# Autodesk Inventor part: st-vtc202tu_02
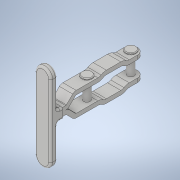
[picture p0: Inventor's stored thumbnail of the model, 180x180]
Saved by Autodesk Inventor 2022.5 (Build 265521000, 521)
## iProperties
Created: 2021-08
Part Number: st-vtc202tu_02
Material: 一般
Document SubType Name: Modeling
Designer: ImaoCorp
Density: 1 g/cm^3
Appearance: 既定
Author: ImaoCorp
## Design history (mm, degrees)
feature "st-vtc202tu_02"
node "ソリッド1"
